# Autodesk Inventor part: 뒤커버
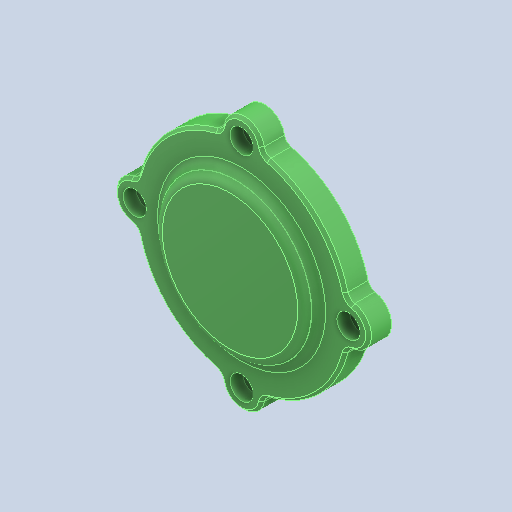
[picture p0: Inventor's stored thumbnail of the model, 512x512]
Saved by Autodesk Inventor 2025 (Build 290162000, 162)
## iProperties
Created: 2024-08
Part Number: 뒤커버
Material: 알루미늄 6061
Document SubType Name: Modeling
Designer: samsung
Density: 2.71 g/cm^3
Appearance: 기본값
Company: 한국ATC센터
Author: jhkim
Sending System: Autodesk Inventor 2025
Preprocessor: ST-DEVELOPER v20
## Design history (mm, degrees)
feature "솔리드1"
node "솔리드2"
